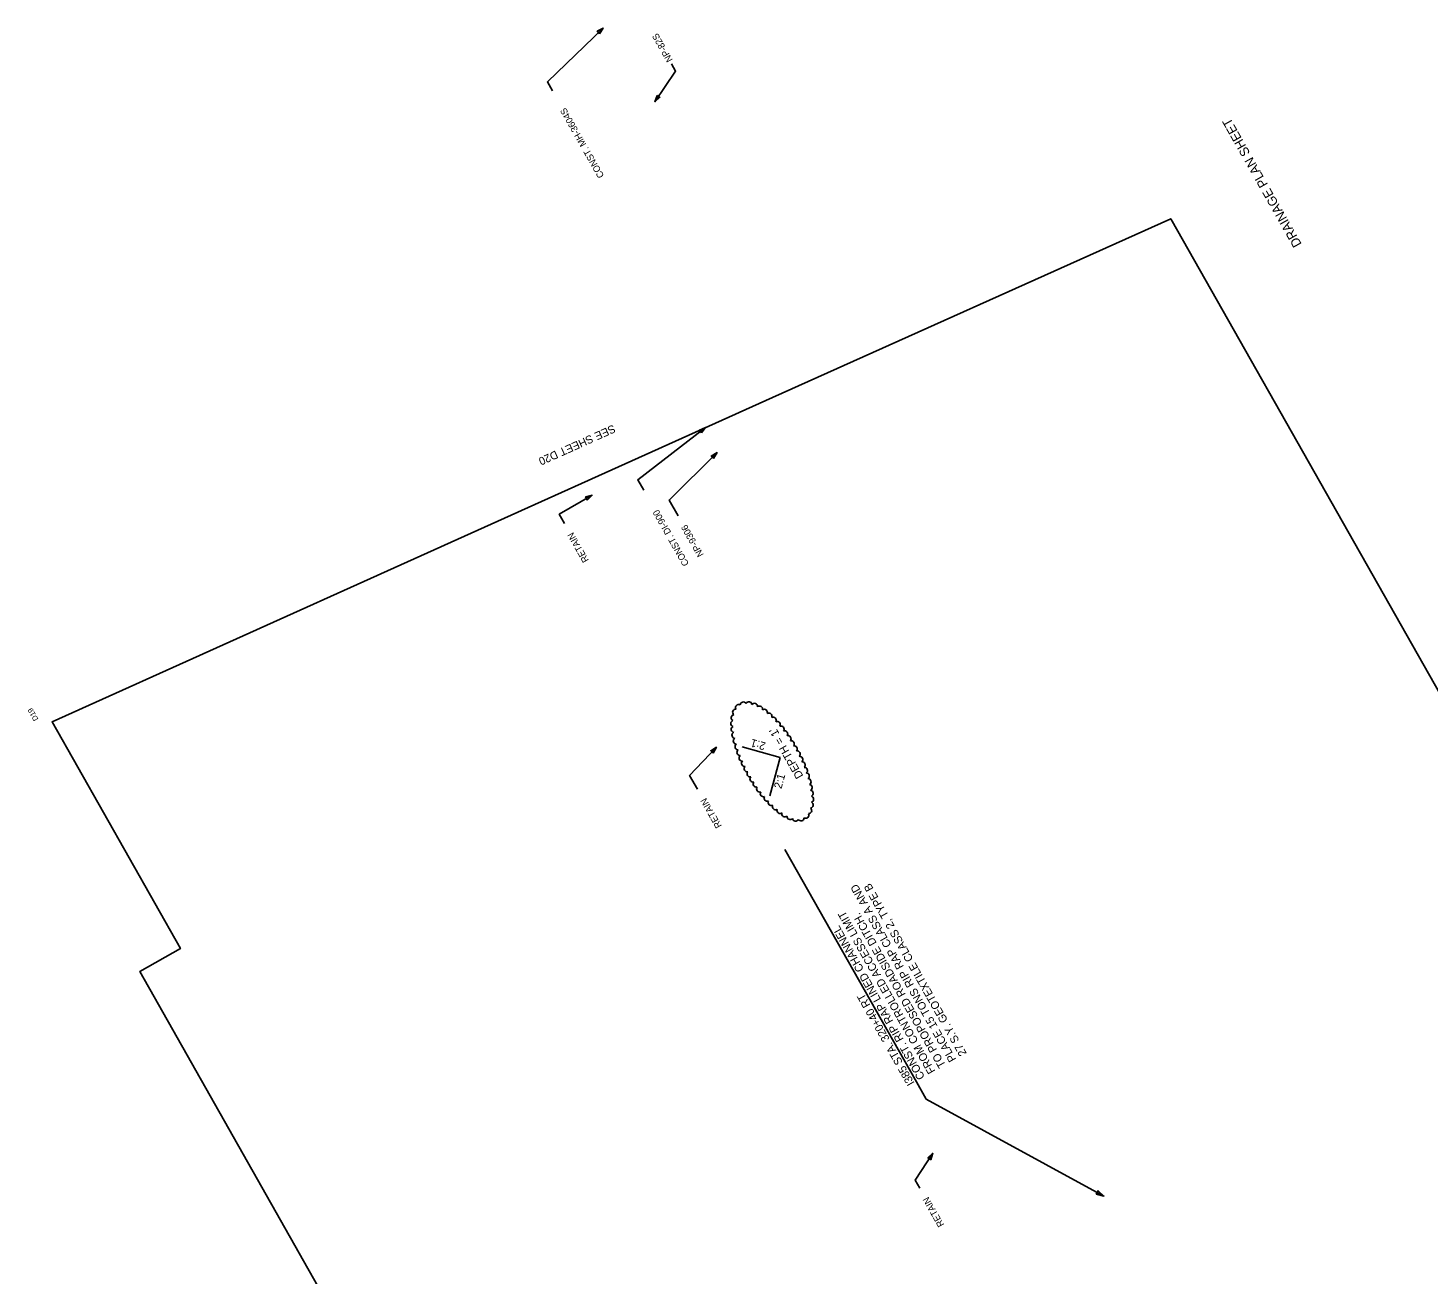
# Model space of a CAD drawing. Extents: x 1612558 to 1614658, y 1085653 to 1087522.
# Drawn here: x 1612558 to 1613608, y 1086587 to 1087522 of the extents above; entities that cross this region are included whole.
import ezdxf

# ---------------------------------------------------------------- set-up
doc = ezdxf.new("R2010")
doc.units = 0
for name, color, linetype in [('Exist Structure Minor Culvert Topo Terminator', 7, 'Continuous'), ('Exist Structure Minor Footbridge', 7, 'Continuous'), ('Exist Structure Minor Footbridge Terminator', 7, 'Continuous'), ('RD_EX_Fence_Other', 7, 'Continuous'), ('RD_HC_Data', 7, 'Continuous'), ('RD_HC_txCode', 7, 'Continuous')]:
    doc.layers.add(name, color=color, linetype=linetype)

msp = doc.modelspace()

# ---------------------------------------------------------------- linework, layer by layer
at = {"layer": 'Exist Structure Minor Footbridge'}
for q in [(1613093.8, 1086983.2), (1613114.6, 1086946.5)]:
    msp.add_line((1613122.5, 1086975.2), q, dxfattribs=at)
at = {"layer": 'Exist Structure Minor Footbridge Terminator'}
msp.add_line((1613125.9, 1086906.3), (1613224.6, 1086732.1), dxfattribs=at)
for points in [[(1612951.7, 1087474.9), (1612947.9, 1087481.6), (1612989.6, 1087521.9)], [(1613040.8, 1087495.2), (1613044, 1087489.5), (1613028.5, 1087466.7)], [(1613020.1, 1087175.6), (1613015.6, 1087183.4), (1613066.5, 1087222.5)], [(1613045.8, 1087156.4), (1613039.1, 1087168.2), (1613075.1, 1087203.7)], [(1612960.7, 1087150.6), (1612956.8, 1087157.5), (1612981.4, 1087171.8)], [(1613060.3, 1086951.5), (1613054.5, 1086961.7), (1613074.6, 1086982.9)], [(1613224.6, 1086732.1), (1613231.9, 1086719.2), (1613365.1, 1086646.5)], [(1613227.1, 1086652.5), (1613223.7, 1086658.5), (1613236.8, 1086678.6)]]:
    msp.add_lwpolyline(points, dxfattribs=at)
for points in [[(1612987, 1087517.7), (1612989.6, 1087521.9), (1612985.2, 1087519.5)], [(1613030.1, 1087471.4), (1613028.5, 1087466.7), (1613032.2, 1087470)], [(1613063.5, 1087218.5), (1613066.5, 1087222.5), (1613061.9, 1087220.6)], [(1613072.5, 1087199.4), (1613075.1, 1087203.7), (1613070.7, 1087201.2)], [(1612977.8, 1087168.2), (1612981.4, 1087171.8), (1612976.5, 1087170.5)], [(1613072.2, 1086978.5), (1613074.6, 1086982.9), (1613070.3, 1086980.3)], [(1613235.3, 1086673.8), (1613236.8, 1086678.6), (1613233.1, 1086675.2)], [(1613359.3, 1086647.9), (1613365.1, 1086646.5), (1613360.7, 1086650.6)]]:
    msp.add_lwpolyline(points, close=True, dxfattribs=at)
for centre, start, end in [((1613089.1, 1087009.2), 85.7666, 230.7666), ((1613091.3, 1087012.6), 62.3338, 207.3338), ((1613094.8, 1087014.5), 31.6988, 176.6988), ((1613098.9, 1087014.7), 8.2661, 153.2661), ((1613103, 1087013.5), 354.4978, 139.4978), ((1613106.9, 1087011.5), 345.9404, 130.9404), ((1613110.5, 1087009), 340.0057, 125.0057), ((1613113.9, 1087006.2), 335.5151, 120.5151), ((1613087.7, 1087000.7), 108.0922, 253.0922), ((1613088, 1087005), 99.5349, 244.5349), ((1613088, 1086996.3), 114.0269, 259.0269), ((1613117.1, 1087003.1), 331.8911, 116.8911), ((1613120.1, 1086999.9), 328.8204, 113.8204), ((1613123, 1086996.5), 326.1163, 111.1163), ((1613088.6, 1086991.9), 118.5176, 263.5176), ((1613089.6, 1086987.6), 122.1415, 267.1415), ((1613125.7, 1086992.9), 323.6584, 108.6584), ((1613128.2, 1086989.3), 321.3628, 106.3628), ((1613130.6, 1086985.5), 319.1661, 104.1661), ((1613090.9, 1086983.3), 125.2123, 270.2123), ((1613092.3, 1086979.1), 127.9164, 272.9164), ((1613132.9, 1086981.7), 317.0163, 102.0163), ((1613135, 1086977.8), 314.8666, 99.8666), ((1613093.9, 1086974.9), 130.3743, 275.3743), ((1613095.8, 1086970.9), 132.6699, 277.6699), ((1613097.7, 1086966.9), 134.8666, 279.8666), ((1613137, 1086973.8), 312.6699, 97.6699), ((1613138.8, 1086969.7), 310.3743, 95.3743), ((1613140.5, 1086965.5), 307.9163, 92.9163), ((1613099.9, 1086963), 137.0163, 282.0163), ((1613102.1, 1086959.1), 139.1661, 284.1661), ((1613104.5, 1086955.4), 141.3627, 286.3627), ((1613141.9, 1086961.3), 305.2122, 90.2122), ((1613143.2, 1086957.1), 302.1416, 87.1416), ((1613107.1, 1086951.7), 143.6584, 288.6584), ((1613109.8, 1086948.2), 146.1163, 291.1163), ((1613112.7, 1086944.8), 148.8204, 293.8204), ((1613144.1, 1086952.7), 298.5177, 83.5177), ((1613144.8, 1086948.4), 294.0272, 79.0272), ((1613145.1, 1086944), 288.0929, 73.0929), ((1613115.7, 1086941.5), 151.8911, 296.8911), ((1613118.9, 1086938.4), 155.5149, 300.5149), ((1613122.3, 1086935.6), 160.0054, 305.0054), ((1613143.7, 1086935.5), 265.7686, 50.7686), ((1613144.8, 1086939.6), 279.5367, 64.5367), ((1613125.9, 1086933.1), 165.9398, 310.9398), ((1613129.8, 1086931.1), 174.496, 319.496), ((1613133.9, 1086929.9), 188.2641, 333.2641), ((1613138, 1086930.1), 211.6986, 356.6986), ((1613141.5, 1086932), 242.3341, 27.3341)]:
    msp.add_arc(centre, 2.35, start, end, dxfattribs=at)
at = {"layer": 'RD_HC_Data'}
msp.add_lwpolyline([(1613343.7, 1085653.3), (1614126.4, 1086125), (1613415.2, 1087379), (1613116.7, 1087245.1), (1612843.1, 1087121.9), (1612576.5, 1087002), (1612672.7, 1086832.1), (1612642.4, 1086814.9), (1613299.9, 1085652.9)], close=True, dxfattribs=at)
msp.add_lwpolyline([(1613343.7, 1085653.3), (1614126.4, 1086125), (1613415.2, 1087379), (1613116.7, 1087245.1), (1612843.1, 1087121.9), (1612576.5, 1087002), (1612672.7, 1086832.1), (1612642.4, 1086814.9), (1613299.9, 1085652.9)], close=True, dxfattribs=at)
msp.add_lwpolyline([(1613343.7, 1085653.3), (1614126.4, 1086125), (1613415.2, 1087379), (1613116.7, 1087245.1), (1612843.1, 1087121.9), (1612576.5, 1087002), (1612672.7, 1086832.1), (1612642.4, 1086814.9), (1613299.9, 1085652.9)], close=True, dxfattribs=at)
msp.add_lwpolyline([(1613343.7, 1085653.3), (1614126.4, 1086125), (1613415.2, 1087379), (1613116.7, 1087245.1), (1612843.1, 1087121.9), (1612576.5, 1087002), (1612672.7, 1086832.1), (1612642.4, 1086814.9), (1613299.9, 1085652.9)], close=True, dxfattribs=at)
msp.add_lwpolyline([(1613343.7, 1085653.3), (1614126.4, 1086125), (1613415.2, 1087379), (1613116.7, 1087245.1), (1612843.1, 1087121.9), (1612576.5, 1087002), (1612672.7, 1086832.1), (1612642.4, 1086814.9), (1613299.9, 1085652.9)], close=True, dxfattribs=at)
msp.add_lwpolyline([(1613343.7, 1085653.3), (1614126.4, 1086125), (1613415.2, 1087379), (1613116.7, 1087245.1), (1612843.1, 1087121.9), (1612576.5, 1087002), (1612672.7, 1086832.1), (1612642.4, 1086814.9), (1613299.9, 1085652.9)], close=True, dxfattribs=at)
msp.add_lwpolyline([(1613343.7, 1085653.3), (1614126.4, 1086125), (1613415.2, 1087379), (1613116.7, 1087245.1), (1612843.1, 1087121.9), (1612576.5, 1087002), (1612672.7, 1086832.1), (1612642.4, 1086814.9), (1613299.9, 1085652.9)], close=True, dxfattribs=at)

# ---------------------------------------------------------------- texts
at = {"layer": 'Exist Structure Minor Culvert Topo Terminator'}
msp.add_text('D19', height=4, rotation=119.5163, dxfattribs=at).set_placement((1612566.4, 1087004))
at = {"layer": 'Exist Structure Minor Footbridge'}
for rotation, p in [(164.5163, (1613112, 1086986.3)), (74.5163, (1613123.3, 1086951.4))]:
    msp.add_text('2:1', height=6, rotation=rotation, dxfattribs=at).set_placement(p)
at = {"layer": 'Exist Structure Minor Footbridge Terminator'}
for s, height, p in [('NP-82S', 5, (1613042, 1087498.1)), ('CONST. MH-3604S', 5, (1612990.6, 1087411.2)), ('CONST. DI-900', 5, (1613054.2, 1087120.4)), ('NP-9306', 5, (1613065.2, 1087127.3)), ('RETAIN', 5, (1612979.1, 1087123.1)), ("DEPTH = 1'", 6, (1613139.9, 1086961.4)), ('RETAIN', 5, (1613078.8, 1086924)), ('PLACE 15 TONS RIP RAP CLASS A AND', 6, (1613254.6, 1086749.1)), ('27 S.Y. GEOTEXTILE CLASS 2, TYPE B', 6, (1613262.4, 1086753.5)), ('FROM CONTROLLED ACCESS LIMIT', 6, (1613238.9, 1086740.2)), ('TO PROPOSED ROADSIDE DITCH.', 6, (1613246.8, 1086744.6)), ('CONST. RIP RAP LINED CHANNEL', 6, (1613231.1, 1086735.8)), ('I385 STA. 320+40 RT', 6, (1613223.3, 1086731.3)), ('RETAIN', 5, (1613245.5, 1086625.1))]:
    msp.add_text(s, height=height, rotation=119.5163, dxfattribs=at).set_placement(p)
at = {"layer": 'RD_EX_Fence_Other'}
msp.add_text('SEE SHEET D20', height=6, rotation=204.2335, dxfattribs=at).set_placement((1612997.2, 1087224.9))
at = {"layer": 'RD_HC_txCode'}
msp.add_text('DRAINAGE PLAN SHEET', height=6.983, rotation=119.5163, dxfattribs=at).set_placement((1613513.6, 1087360))

doc.saveas('drawing.dxf')
